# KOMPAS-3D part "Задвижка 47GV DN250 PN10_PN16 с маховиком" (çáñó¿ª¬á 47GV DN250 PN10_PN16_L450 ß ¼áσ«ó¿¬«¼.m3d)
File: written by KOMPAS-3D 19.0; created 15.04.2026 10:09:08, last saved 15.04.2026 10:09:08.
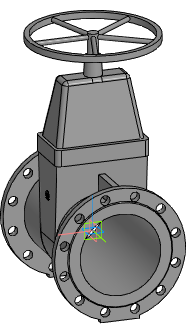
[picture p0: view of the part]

Document properties: Автор: Евгений; Полное имя файла: Z:\3.Личные\kachalov\3d для проектировщиков\2.1 Тип 47GV, 47GV.Z\Задвижка 47GV_DN40-DN600\stp_Задвижка 47GV\Задвижка 47GV DN250 PN10_PN16_L450 с маховиком.m3d

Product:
- Part/product: Задвижка 47GV DN250 PN10_PN16 с маховиком

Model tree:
1. Операция без истории:1  (labels: Задвижка 47GV DN250 PN10_PN16 с маховиком)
